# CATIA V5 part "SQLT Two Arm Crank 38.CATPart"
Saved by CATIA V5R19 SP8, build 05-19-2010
Part number: SQLT Two Arm Crank 38
Publications: "Plan.1", "Droite.1", "Droite.2", "Plan.2", "Droite.3"
Bounding box of the stored display mesh (mm): x -50 to 50, y 669.645 to 740.355, z 439.645 to 510.355
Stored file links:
  G:\EU_thinkMotion\CFAO_2010\MMS_groupe3\MMS_groupe3\A reprendre\fovide\fovide\SQLT Two Arm Crank 38.CATPart
  G:\EU_thinkMotion\CFAO_2010\MMS_groupe3\MMS_groupe3\A reprendre\fovide\fovide\fovide.CATProduct
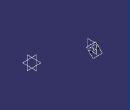
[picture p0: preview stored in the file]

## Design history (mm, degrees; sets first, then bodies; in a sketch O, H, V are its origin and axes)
Set1
  Point1 "Point.K": linked copy from another document
  Point2 "Point.L": linked copy from another document
  Plane1: linked copy from another document
Set2 "set Two Arm Crank 38"
  Line1: type PtPt, FirstPoint Point1, SecondPoint Point2
  Plane2: type OffsetPt, RefPlane yz-plane, RefPoint Point2
  Line2: type Normal, RefPoint Point2, RefSkin Plane2, Start -50, End 50
  Plane3: type OffsetPt, RefPlane Plane1, RefPoint Point1
  Line3: type Normal, RefPoint Point1, RefSkin Plane3, Start -50, End 50
Body1 (main body)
